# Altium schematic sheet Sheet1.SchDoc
size A; SheetNumber: 1; SheetTotal: 1
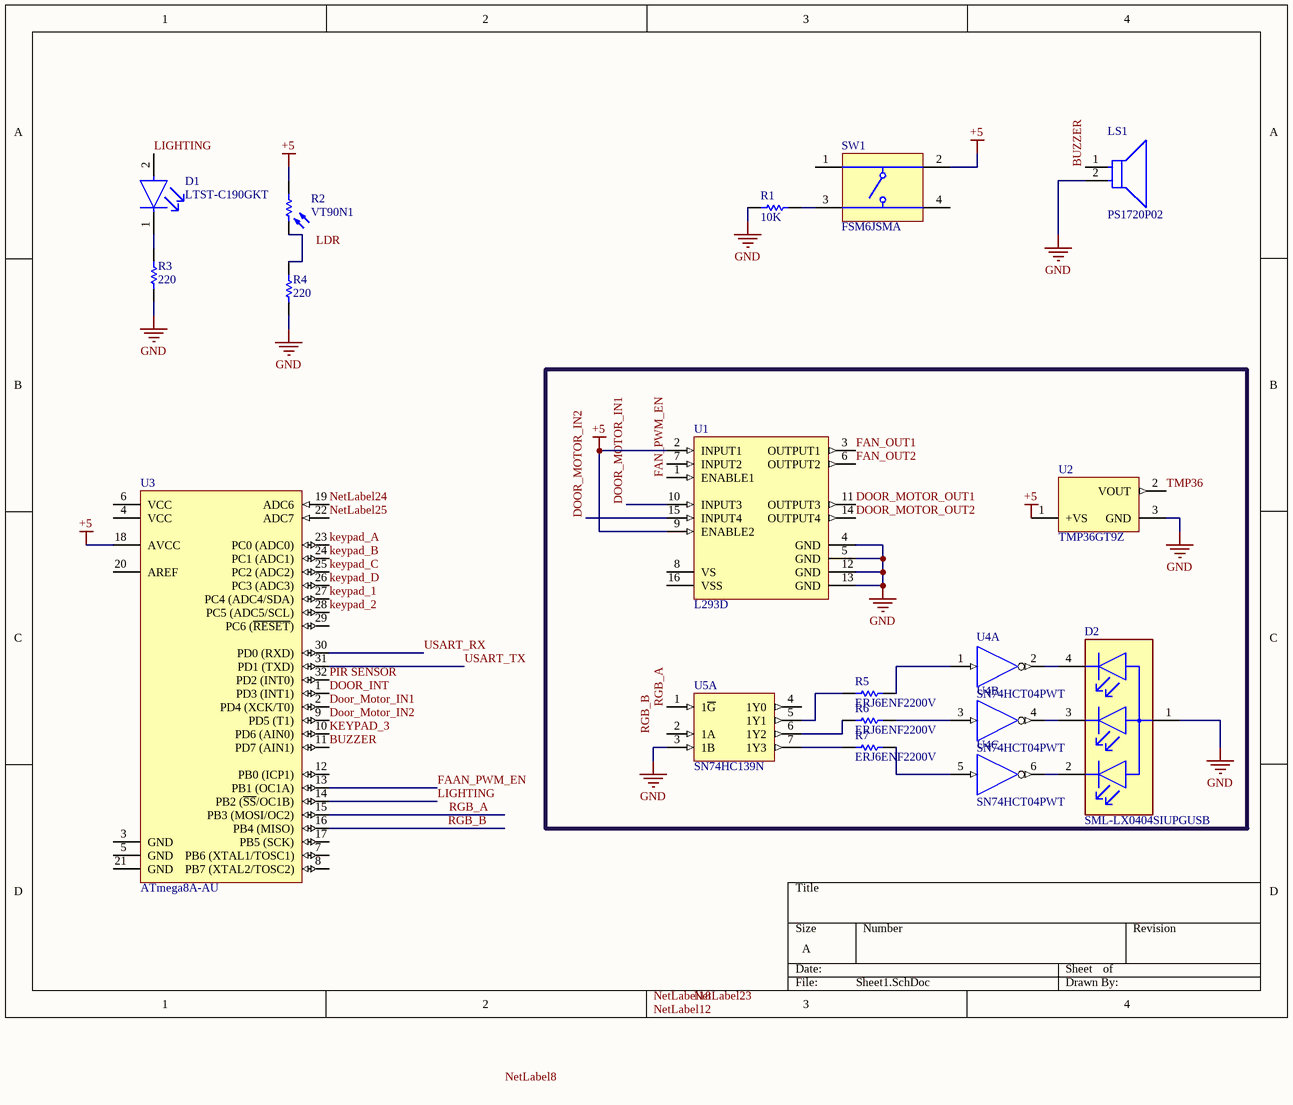
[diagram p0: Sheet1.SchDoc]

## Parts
D1  LTST-C190GKT  [FP-LTST-C190GKT-MFG]
D2  SML-LX0404SIUPGUSB  [FP-SML-LX0404SIUPGUSB-MFG]
LS1  PS1720P02  [FP-PS1720P02-MFG]
R1  value 10K  (hidden comment: Resistor)
R2  VT90N1  [EXCE-VT90N1]
R3  value 220  (hidden comment: Resistor)
R4  value 220  (hidden comment: Resistor)
R5  ERJ6ENF2200V  [RESC2013X70X40NL20T20]
R6  ERJ6ENF2200V  [RESC2013X70X40NL20T20]
R7  ERJ6ENF2200V  [RESC2013X70X40NL20T20]
SW1  FSM6JSMA  [TECO-FSM6JSMA_V]
U1  L293D  [STM-L293D-16]
U2  TMP36GT9Z  [ADI-T-3]
U3  ATmega8A-AU  [32A_N]
U4  SN74HCT04PWT  [PW0014A_N]  (parts A,B,C of 7)
U5  SN74HC139N  [N0016A]  (part A of 3)

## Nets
+5: R2.1 SW1.2 U1.2(INPUT1) U1.9(ENABLE2) U2.1(+VS) U3.18(AVCC)
GND: D2.1(Common_Anode) LS1.2 R1.1 R3.1 R4.1 U1.4(GND) U1.5(GND) U1.12(GND) U1.13(GND) U2.3(GND) U5.3(1B)
BUZZER: LS1.1 U3.11(PD7_(AIN1))
DOOR_INT: U3.1(PD3_(INT1))
Door_Motor_IN1: U1.10(INPUT3) U3.2(PD4_(XCK/T0))
Door_Motor_IN2: U1.15(INPUT4) U3.9(PD5_(T1))
DOOR_MOTOR_OUT1: U1.11(OUTPUT3)
DOOR_MOTOR_OUT2: U1.14(OUTPUT4)
FAAN_PWM_EN: U3.13(PB1_(OC1A))
FAN_OUT1: U1.3(OUTPUT1)
FAN_OUT2: U1.6(OUTPUT2)
FAN_PWM_EN: U1.1(ENABLE1)
keypad_1: U3.27(PC4_(ADC4/SDA))
keypad_2: U3.28(PC5_(ADC5/SCL))
KEYPAD_3: U3.10(PD6_(AIN0))
keypad_A: U3.23(PC0_(ADC0))
keypad_B: U3.24(PC1_(ADC1))
keypad_C: U3.25(PC2_(ADC2))
keypad_D: U3.26(PC3_(ADC3))
LIGHTING: D1.2(A) U3.14(PB2_(~{SS}/OC1B))
NetLabel24: U3.19(ADC6)
NetLabel25: U3.22(ADC7)
PIR SENSOR: U3.32(PD2_(INT0))
RGB_A: U3.15(PB3_(MOSI/OC2)) U5.1(1~{G})
RGB_B: U3.16(PB4_(MISO))
TMP36: U2.2(VOUT)
USART_RX: U3.30(PD0_(RXD))
USART_TX: U3.31(PD1_(TXD))
NetD1_1: D1.1(C) R3.2
NetD2_2: D2.2(Red_C) U4.6(~{3Y})
NetD2_3: D2.3(Blue_C) U4.4(~{2Y})
NetD2_4: D2.4(Green_C) U4.2(~{1Y})
NetR1_2: R1.2 SW1.3
NetR2_2: R2.2 R4.2
NetR5_1: R5.1 U5.5(1Y1)
NetR5_2: R5.2 U4.1(1A)
NetR6_1: R6.1 U5.6(1Y2)
NetR6_2: R6.2 U4.3(2A)
NetR7_1: R7.1 U5.7(1Y3)
NetR7_2: R7.2 U4.5(3A)

Not connected (* = marked no-connect by the designer): SW1 1 4; U1 7(INPUT2) 8(VS) 16(VSS); U3 3(GND) 4(VCC) 5(GND) 6(VCC) 7(PB6_(XTAL1/TOSC1)) 8(PB7_(XTAL2/TOSC2)) 12(PB0_(ICP1)) 17(PB5_(SCK)) 20(AREF) 21(GND) 29(PC6_(~{RESET})); U5 2(1A) 4(1Y0)

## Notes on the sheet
- Labels drawn without touching a wire or pin: LDR, NetLabel8, NetLabel12, NetLabel18, NetLabel23, RGB_B

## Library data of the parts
D1 = CMP-22017-000005-2: LED GREEN CLEAR CHIP SMD; Dominant Wavelength: 569nm; Reverse Voltage: 5V; Lens Color: Colorless; Viewing Angle: 130°; Voltage: 2V; Forward Current: 30mA; Power Dissipation: 100mW; Luminous Intensity: 6mcd; Number of LEDs: 1; Forward Voltage: 2.1V; Wavelength: 565nm; Test Current: 10mA
D2 = CMP-2000-07119-2: LED RGB CLEAR SMD; Test Current: 2mA; Wavelength: 465nm; Color: Blue; Lens Style: Square; Power Rating: 30mW; Lens Color: Colorless; Number of LEDs: 3; Viewing Angle: 120°; Luminous Intensity: 20mcd; Forward Voltage: 2.73V
LS1 = CMP-08413-000001-1: AUDIO PIEZO TRANSDUCER 30V TH; Manufacturer: TDK Corporation; Description: Audio Buzzer Piezo 3Vo-p Pin Through Hole; Frequency: 2kHz; Standoff Height: 0.5mm
R1 R3 R4 = Resistor: TC1: 0; SimulationGenericComponent: True
R2 = CMP-2000-07406-1: Photoconductive Resistor, 200 kOhm, 100 V, 80 mW, -40 to 75 degC, 2-Pin THD, RoHS; Manufacturer: Excelitas Technology; SVHC: Cadmiumchloride(15-Jun-2015); Power Rating: 80mW; Resistance @ Lux: 12kohm; Voltage Rating: 100V
R5-R7 = CMP-2001-00044-1: Manufacturer: Panasonic
SW1 = CMP-2000-07503-1: Switch, SPST, 24 V, -35 to 85 degC, 4-Pin SMD, RoHS, Tape and Reel; Manufacturer: TE Connectivity; Electrical Life: 100000Cycles; Voltage Rating (DC): 24V; Contact Resistance: 100mOhm; Case\/Package: SMD/SMT; Actuator Length: 3.4mm; Contact Current Rating: 50mA; Operating Force: 1.57N; Max Voltage Rating (DC): 12V; Illumination Type: Illuminated; Actuator Material: Polyamide; Switch Travel: 0.25mm
U1 = CMP-2000-06524-1: Push-Pull Four Channel Driver with Diode, 4.5 to 36 V, -40 to 150 degC, 16-Pin PDIP, RoHS, Tube; Manufacturer: STMicroelectronics; Number of Outputs: 4; Current - Peak Output: 1.2A; Current - Output / Channel: 600mA; Input Type: Non-Inverting; Other Related Documents: L293DViewAllSpecifications; Dynamic Catalog: HalfBridge; Voltage - Supply: 4.5V~36V; Other Names: 497-2936-5
U2 = CMP-0887-00067-1: Low Voltage Temperature Sensor, 2.7 to 5.5 V Supply, Industrial, 3-pin TO92 (T-3), Tray; Manufacturer: Analog Devices
U3 = CMP-0095-00219-2: 8-bit AVR Microcontroller, 2.7-5.5V, 16MHz, 8KB Flash, 512 Bytes EEPROM, 1KB SRAM, 32-pin TQFP, Industrial Grade (-40°C to 85°C)
U4 = CMP-1615-00087-3: Hex Inverters, PW0014A, SMALL T&R; Manufacturer: Texas Instruments; tpd @ Nom Voltage(Max)(ns): 23; Rating: Catalog; Output Type: CMOS; Bits(#): 6; Input Type: TTL; F @ Nom Voltage(Max)(Mhz): 25; Output Drive (IOL/IOH)(Max)(mA): -4/4; Voltage(Nom)(V): 5; ICC @ Nom Voltage(Max)(mA): 0.02; VCC(Min)(V): 4.5; Schmitt Trigger: No; VCC(Max)(V): 5.5; Technology Family: HCT
U5 = CMP-1633-00660-2: Dual 2-Line To 4-Line Decoders/Demultiplexers, N0016A, TUBE; Manufacturer: Texas Instruments; Technology Family: HC; VCC(Min)(V): 2; Voltage(Nom)(V): 3.3,5; F @ Nom Voltage(Max)(Mhz): 28; Output Type: CMOS; Bits(#): 4; VCC(Max)(V): 6; ICC @ Nom Voltage(Max)(mA): 0.08; Function: Decoder/Demultiplexer; Input Type: LVTTL/CMOS; Output Drive (IOL/IOH)(Max)(mA): 5.2/-5.2; Schmitt Trigger: No; Rating: Catalog; Configuration: 2：4; tpd @ Nom Voltage(Max)(ns): 44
